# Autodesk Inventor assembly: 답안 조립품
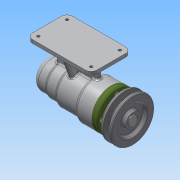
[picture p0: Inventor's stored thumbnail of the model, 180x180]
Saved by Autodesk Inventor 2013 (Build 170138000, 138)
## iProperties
Created: 2016-06
Part Number: 답안 조립품
Document SubType Name: Assembly
Designer: Administrator
Author: Administrator
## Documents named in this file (12)
- C:\Users\Administrator\Desktop\460608V1002\답안 조립품.iam
- C:\Users\Administrator\Desktop\460608V1002\본체.ipt
- C:\Users\Administrator\Desktop\460608V1002\V벨트풀리.ipt
- C:\Users\Administrator\Desktop\460608V1002\멈춤나사 M3x8.ipt
- C:\Users\Administrator\Desktop\460608V1002\베어링 6004.ipt
- C:\Users\Administrator\Desktop\460608V1002\베어링 51202.ipt
- C:\Users\Administrator\Desktop\460608V1002\볼트 M4 x 12.ipt
- C:\Users\Administrator\Desktop\460608V1002\어댑터슬리브.ipt
- C:\Users\Administrator\Desktop\460608V1002\오일 실.ipt
- C:\Users\Administrator\Desktop\460608V1002\축.ipt
- C:\Users\Administrator\Desktop\460608V1002\커버.ipt
- C:\Users\Administrator\Desktop\460608V1002\키 5 x 5 x 16.ipt
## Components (5 placed, 2 different names)
1. V벨트풀리:1 — 플러쉬:1
2. ISO 4762 M4 x 12:1
3. ISO 4762 M4 x 12:2
4. ISO 4762 M4 x 12:3
5. ISO 4762 M4 x 12:4
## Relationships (1: Flush 1)
- 플러쉬:1 [Flush]: V벨트풀리:1
